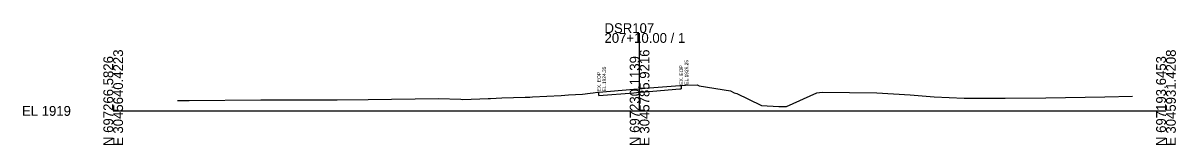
# Model space of a CAD drawing. Extents: x -26 to 19003, y -31 to 24541.
# Drawn here: x 1974.3 to 2302.8, y 18490.3 to 18525 of the extents above; entities that cross this region are included whole.
import ezdxf

# ---------------------------------------------------------------- set-up
doc = ezdxf.new("R2010")
doc.units = 0
for name, color, linetype in [('DESIGN - SHEET - Light Grid', 7, 'Continuous'), ('SURVEY - GROUND - Existing Pavement Layer', 7, 'Continuous'), ('SURVEY - GROUND - Existing Pavement Text', 7, 'Continuous'), ('SURVEY - GROUND - Top of Ground', 7, 'Continuous')]:
    doc.layers.add(name, color=color, linetype=linetype)

msp = doc.modelspace()

# ---------------------------------------------------------------- linework, layer by layer
at = {"layer": 'DESIGN - SHEET - Light Grid'}
for p, q in [((2150, 18500), (2150, 18522.17)), ((2000, 18500), (2150, 18500)), ((2150, 18500), (2300, 18500))]:
    msp.add_line(p, q, dxfattribs=at)
at = {"layer": 'SURVEY - GROUND - Existing Pavement Layer'}
for p, q in [((2151.54, 18505.45), (2161.48, 18506.24)), ((2161.48, 18506.24), (2161.85, 18506.25)), ((2161.85, 18507.25), (2161.85, 18506.25)), ((2138.41, 18504.35), (2138.41, 18505.35)), ((2138.41, 18504.35), (2148.34, 18505.19)), ((2148.34, 18505.19), (2149.92, 18505.33)), ((2149.92, 18505.33), (2151.54, 18505.45))]:
    msp.add_line(p, q, dxfattribs=at)
at = {"layer": 'SURVEY - GROUND - Top of Ground'}
msp.add_lwpolyline([(2018.34, 18502.96), (2021.67, 18502.98), (2042.04, 18503.17), (2052.15, 18503.19), (2063.83, 18503.15), (2072.62, 18503.28), (2092.73, 18503.56), (2099.02, 18503.37), (2099.63, 18503.29), (2106.86, 18503.53), (2107.55, 18503.57), (2110.78, 18503.68), (2117.4, 18503.9), (2118.68, 18503.92), (2119.47, 18503.96), (2127.69, 18504.4), (2129.75, 18504.56), (2133.71, 18504.75), (2135.89, 18505.02), (2136.76, 18505.12), (2138.04, 18505.31), (2138.41, 18505.35), (2148.34, 18506.19), (2149.92, 18506.33), (2151.54, 18506.45), (2161.48, 18507.24), (2161.85, 18507.25), (2162.8, 18507.31), (2163.12, 18507.31), (2166.39, 18507.39), (2166.97, 18507.18), (2175.89, 18505.67), (2176.94, 18505.14), (2177.71, 18504.91), (2180.99, 18503.36), (2184.7, 18501.55), (2189.63, 18501.23), (2191.82, 18501.22), (2200.5, 18505.12), (2201.23, 18505.27), (2202.05, 18505.34), (2217.61, 18505.14), (2227.1, 18504.56), (2233.93, 18504.05), (2242.47, 18503.64), (2254.19, 18503.59), (2265.78, 18503.73), (2282.56, 18504.02), (2290.5, 18504.17)], dxfattribs=at)

# ---------------------------------------------------------------- texts
at = {"layer": 'DESIGN - SHEET - Light Grid'}
for s, p in [('DSR107', (2140, 18522.17)), ('207+10.00 / 1', (2140, 18519.37)), ('EL 1919', (1974, 18498.6))]:
    msp.add_text(s, height=2.8, dxfattribs=at).set_placement(p)
for s, p in [('E 3045640.4223', (2002.8, 18490)), ('E 3045785.9216', (2152.8, 18490)), ('E 3045931.4208', (2302.8, 18490)), ('N 697266.5826', (2000, 18490)), ('N 697230.1139', (2150, 18490)), ('N 697193.6453', (2300, 18490))]:
    msp.add_text(s, height=2.8, rotation=90, dxfattribs=at).set_placement(p)
at = {"layer": 'SURVEY - GROUND - Existing Pavement Text'}
for s, p in [('EL.1926.25', (2163.85, 18507.45)), ('EX. EOP', (2138.91, 18505.55)), ('EL.1924.35', (2140.41, 18505.55)), ('EX. EOP', (2162.35, 18507.45))]:
    msp.add_text(s, height=1, rotation=90, dxfattribs=at).set_placement(p)

doc.saveas('drawing.dxf')
